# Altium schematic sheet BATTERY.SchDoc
size 420 x 297 mm
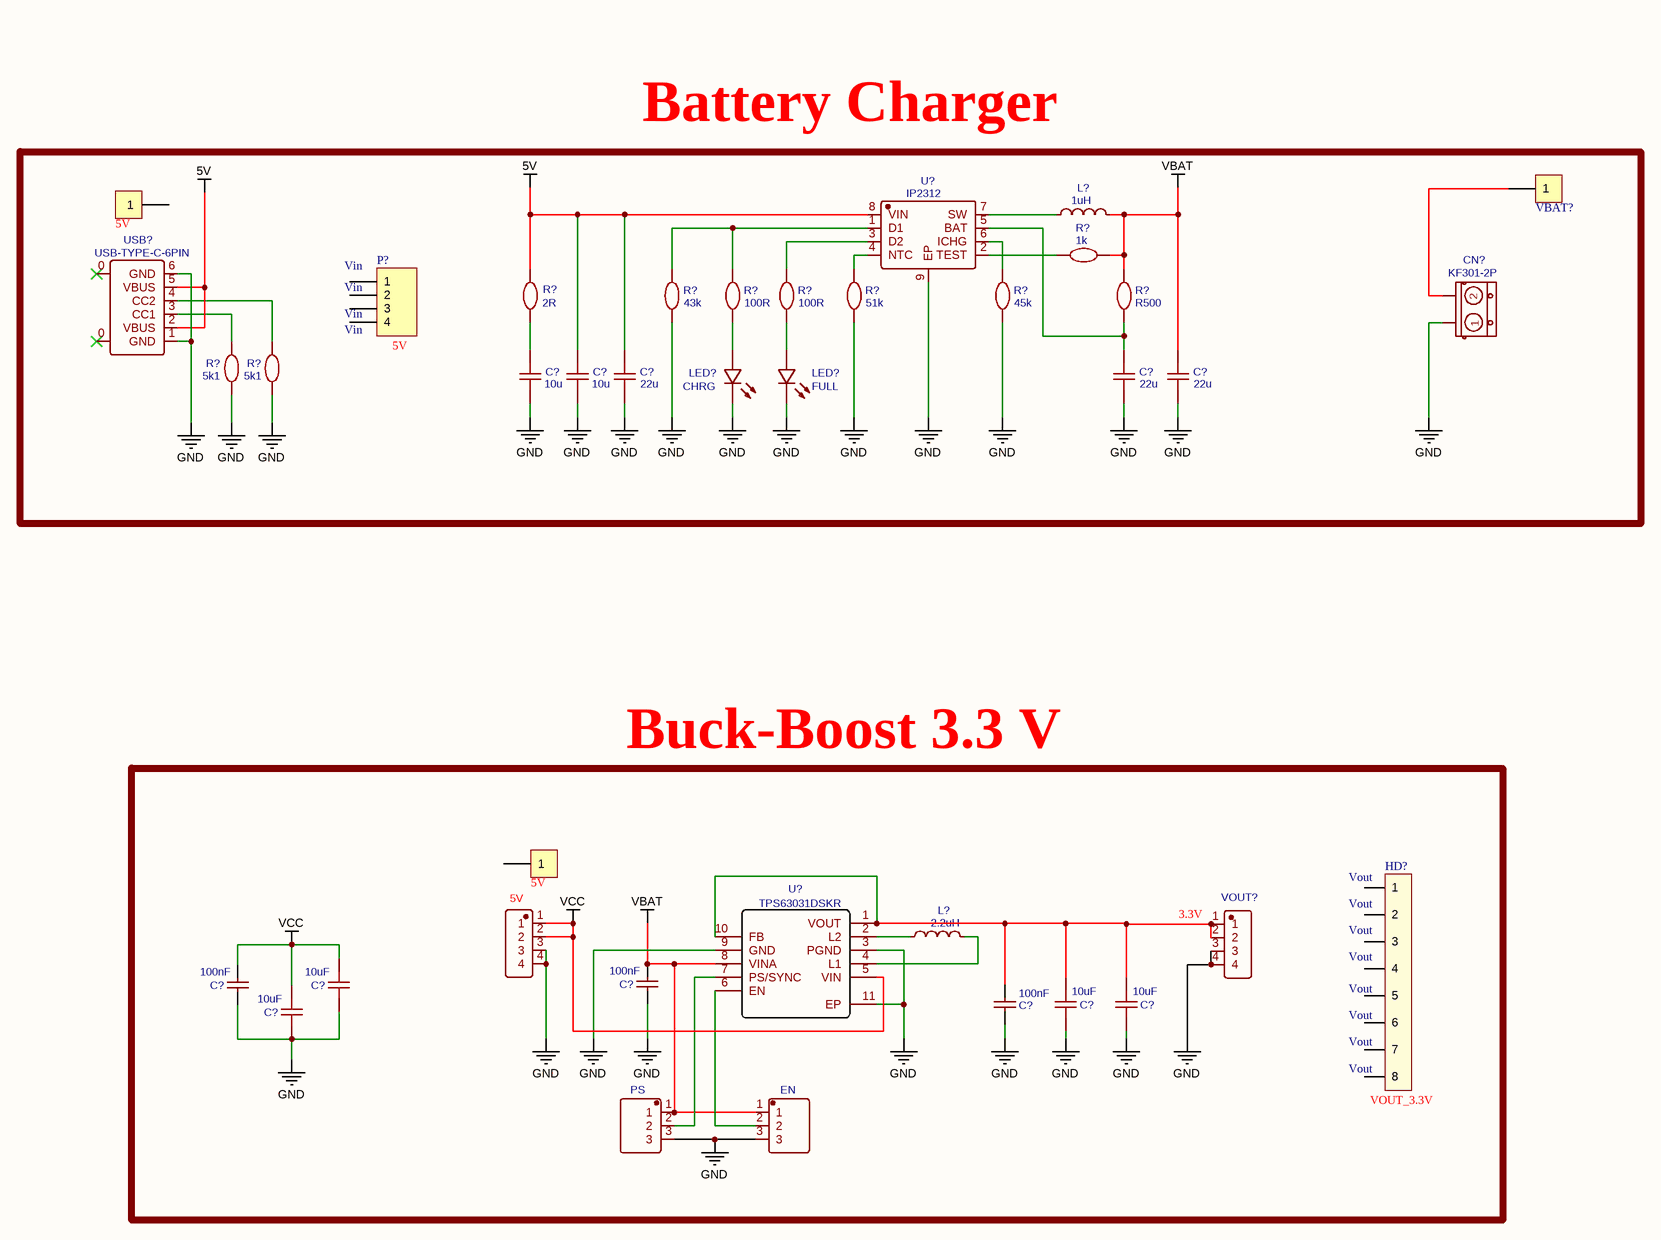
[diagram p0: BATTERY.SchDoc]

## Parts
(Parts that share a designator on the sheet are numbered #1, #2 ... from top to bottom, then left to right.)
5V#1  Header 1  [HEAD1]  (value not drawn)
5V#2  Header 1  [HEAD1]  (value not drawn)
5V#3  Z-211-0411-0021-001  [HDR-TH_4P-P2.54-V]  (value not drawn)
C?#1  10u  [C_0603]
C?#2  10u  [C_0603]
C?#3  22u  [C_0603]
C?#4  22u  [C_0603]
C?#5  22u  [C_0603]
C?#6  100nF  [C0805]
C?#7  100nF  [C0805]
C?#8  10uF  [C1206]
C?#9  100nF  [C0805]
C?#10  10uF  [C1206]
C?#11  10uF  [C1206]
C?#12  10uF  [C1206]
CN?  KF301-2P  [KF301-2P]
EN  RE-H032TD-1130  [HDR-TH_3P-P2.54-V]  (value not drawn)
HD?  VOUT_3.3V  [HED8V]
L?#1  1uH  [IND-706628_IND_0630_VAN]
L?#2  2.2uH  [IND-SMD_L7.1-W6.6]
LED?#1  CHRG  [LED_0603]
LED?#2  FULL  [LED_0603]
P?  5V  [HDR1X4]
PS  RE-H032TD-1130  [HDR-TH_3P-P2.54-V]  (value not drawn)
R?#1  1k  [0603]
R?#2  2R  [0603]
R?#3  43k  [0603]
R?#4  100R  [0603]
R?#5  100R  [0603]
R?#6  51k  [0603]
R?#7  45k  [0603]
R?#8  R500  [0603]
R?#9  5k1  [0603]
R?#10  5k1  [0603]
U?#1  IP2312  [SOP-8_EP_150MIL]
U?#2  TPS63031DSKR  [SON-10_L2.5-W2.5-P0.50-TL-EP]
USB?  USB-TYPE-C-6PIN  [USB-C-SMD-6P]
VBAT?  Header 1  [HEAD1]  (value not drawn)
VOUT?  Z-211-0411-0021-001  [HDR-TH_4P-P2.54-V]  (value not drawn)

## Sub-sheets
? = Buck-Boost 3.3 V: no entries
? = ?: no entries

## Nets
5V: C?#2.1 C?#3.1 R?#2.2 U?#1.8(VIN) USB?.2(VBUS) USB?.5(VBUS)
GND: 5V#3.3 5V#3.4 C?#1.2 C?#2.2 C?#3.2 C?#4.2 C?#5.2 C?#6.2 C?#7.2 C?#8.2 C?#9.2 C?#10.2 C?#11.2 C?#12.1 CN?.1 EN.3 LED?#1.2(K) LED?#2.2(C) PS.3 R?#3.2 R?#6.1 R?#7.2 R?#9.2 R?#10.2 U?#1.9(EP) U?#2.3(PGND) U?#2.9(GND) U?#2.11(EP) USB?.1(GND) USB?.6(GND) VOUT?.3 VOUT?.4
VBAT: C?#5.1 C?#6.1 EN.1 L?#1.2 PS.1 R?#1.2 R?#8.2 U?#2.8(VINA)
VCC: 5V#3.1 5V#3.2 C?#7.1 C?#8.1 C?#12.2 U?#2.5(VIN)
NetC?#1_1: C?#1.1 R?#2.1
NetC?#4_1: C?#4.1 R?#8.1 U?#1.5(BAT)
NetC?#9_1: C?#9.1 C?#10.1 C?#11.1 U?#2.1(VOUT) U?#2.10(FB) VOUT?.1 VOUT?.2
NetCN?_2: CN?.2 VBAT?.1
NetEN_2: EN.2 U?#2.6(EN)
NetL?#1_1: L?#1.1 U?#1.7(SW)
NetL?#2_1: L?#2.1 U?#2.2(L2)
NetL?#2_2: L?#2.2 U?#2.4(L1)
NetLED?#1_1: LED?#1.1(A) R?#4.2
NetLED?#2_1: LED?#2.1(A) R?#5.2
NetPS_2: PS.2 U?#2.7(PS/SYNC)
NetR?#1_1: R?#1.1 U?#1.2(TEST)
NetR?#3_1: R?#3.1 R?#4.1 U?#1.1(D1)
NetR?#5_1: R?#5.1 U?#1.3(D2)
NetR?#6_2: R?#6.2 U?#1.4(NTC)
NetR?#7_1: R?#7.1 U?#1.6(ICHG)
NetR?#9_1: R?#9.1 USB?.3(CC1)
NetR?#10_1: R?#10.1 USB?.4(CC2)

Not connected (* = marked no-connect by the designer): 5V#1 1; 5V#2 1; HD? 1 2 3 4 5 6 7 8; P? 1 2 3 4; USB? 0(SHIELD)*

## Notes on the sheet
- Battery Charger
- (near P?) Vin
- (near VOUT?) 3.3V
- (near HD?) Vout

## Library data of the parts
5V#1 5V#2 VBAT? = Header 1: Header, 1-Pin, Right Angle; Revised: Zion Blue
5V#3 VOUT? = Z-211-0411-0021-001: BOM_Manufacturer: ZHENGLING; Contributor: LCSC
C?#1 C?#2 = 10u: Manufacturer: SAMSUNG; Manufacturer Part: CL10A106KP8NNNC; nameAlias: Capacitance
C?#3-C?#5 = 22u: Manufacturer: MuRata; Manufacturer Part: GRM188R60J226MEA0D; nameAlias: Capacitance
C?#6 C?#7 C?#9 = 100nF: BOM_Manufacturer Part: CL21B104KCFNNNE; BOM_Manufacturer: SAMSUNG; nameAlias: Capacitance; SMT Type: Extend
C?#8 C?#10-C?#12 = 10uF: BOM_Manufacturer: SAMSUNG; BOM_Manufacturer Part: CL31B106KBHNNNE; nameAlias: Capacitance; SMT Type: Extend
CN? = KF301-2P: Manufacturer Part: KF301-5.0-2P; Manufacturer: Cixi Kefa Elec; Contributor: vonk0031; sourceId: Z5gQ20Ay7
EN PS = RE-H032TD-1130: BOM_Manufacturer: JST Sales America; Contributor: LCSC
HD? = Header 8: Header 8 Vit Broad
L?#1 = 1uH: Manufacturer: Prosperity Dielectrics; Manufacturer Part: MCS0630-1R0MN2; nameAlias: Inductance; Contributor: vankul27
L?#2 = 2.2uH: BOM_Manufacturer: Sunlord; BOM_Manufacturer Part: MWSA0603-2R2MT; nameAlias: Inductance; SMT Type: Extend
LED?#1 = CHRG: Manufacturer: KENTO; Manufacturer Part: KT-0603R; SMT Type: Basic; Contributor: Stefan Wagner
LED?#2 = FULL: Manufacturer: EVERLIGHT; Manufacturer Part: 19-217/GHC-YR1S2/3T; SMT Type: Basic; Contributor: Stefan Wagner
P? = Header 4: Header, 4-Pin, Right Angle
R?#1 = 1k: Manufacturer Part: 0603WAF1001T5E; Manufacturer: UNI-ROYAL(厚声); nameAlias: Value(Ω)
R?#2 = 2R: Manufacturer Part: 0603WAJ020JT5E; Manufacturer: UniOhm; nameAlias: Value(Ω)
R?#3 = 43k: Manufacturer Part: 0603WAF4302T5E; Manufacturer: UNI-ROYAL(厚声); nameAlias: Value(Ω)
R?#4 R?#5 = 100R: Manufacturer Part: 0603WAF1000T5E; Manufacturer: UNI-ROYAL(厚声); nameAlias: Value(Ω)
R?#6 = 51k: Manufacturer Part: 0603WAF5102T5E; Manufacturer: UniOhm; nameAlias: Value(Ω)
R?#7 = 45k: Manufacturer Part: 0603WAF4532T5E; Manufacturer: UniOhm; nameAlias: Value(Ω)
R?#8 = R500: Manufacturer Part: FRL0603JR500TS; Manufacturer: FOJAN; nameAlias: Value(Ω); Package Display: No
R?#9 R?#10 = 5k1: Manufacturer Part: 0603WAF5101T5E; Manufacturer: UniOhm; nameAlias: Value(Ω)
U?#1 = IP2312: Manufacturer: INJOINIC(英集芯); Manufacturer Part: IP2312U_VSET; Contributor: Stefan Wagner
U?#2 = TPS63031DSKR: BOM_Manufacturer: TI; SMT Type: Extend
USB? = USB-TYPE-C-6PIN: Manufacturer: Korean Hroparts Elec; Manufacturer Part: TYPE-C-31-M-17; Contributor: Stefan Wagner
